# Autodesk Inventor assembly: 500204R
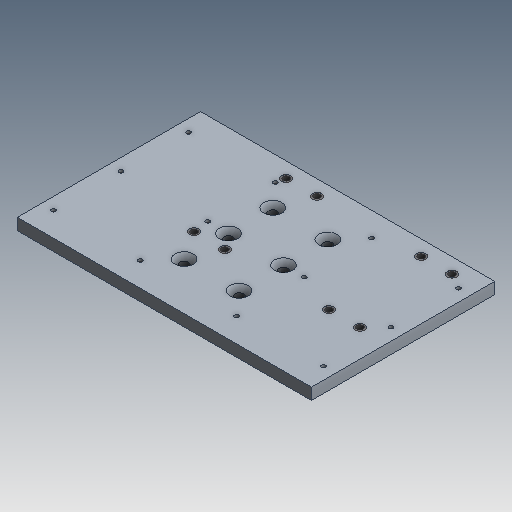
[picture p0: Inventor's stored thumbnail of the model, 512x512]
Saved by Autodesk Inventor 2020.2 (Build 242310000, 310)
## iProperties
Created: 1999-12
Part Number: 500204R
Description: PLT-CP,FA,XX,05,120,075,PLATE,MNT
Document SubType Name: Assembly
Designer: tgregory
Mass: 1875.54 g
Surface Area: 1401.55 cm^2
Volume: 683.002 cm^3
Density: 2.74602 g/cm^3
Control State: 0
Checked Out: False
Master: False
Shininess: 0.0
Length Units: 11272
Angle Units: 11279
Time Units: 11290
Mass Units: 11286
Length Display Precision: 3
Angle Display Precision: 2
Compacted: True
Dimensions: 7,5x0,5x12 in
Mass: 4,135 lb
DocNumber: 500204R.iam
Folder: 01 - Themengebiete\Simplification\01 - Packaging machine\
VDS_Category: 3D Komponenten
Density: 0.0
Volumn: 0.0
Area: 0.0
PropertySet Name: Model Information
Author: tgregory
Revision Number: -
Title: PLT-CP,FA,XX,05,120,075,PLATE,MNT
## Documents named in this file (4)
- D:\07 - DEMODATEN\OTX 2019 - Dataset - UPDATE - Dez2019\Designs\07-Packing machine\500204R.iam
- D:\07 - DEMODATEN\OTX 2019 - Dataset - UPDATE - Dez2019\Designs\07-Packing machine\Parts\ADSK-011301.ipt
- D:\07 - DEMODATEN\OTX 2019 - Dataset - UPDATE - Dez2019\Designs\07-Packing machine\Parts\ADSK-011735.ipt
- D:\07 - DEMODATEN\OTX 2019 - Dataset - UPDATE - Dez2019\Designs\07-Packing machine\Parts\ADSK-011736.ipt
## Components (21 placed, 3 different names)
1. ADSK-011301:1 — Insert:1, Insert:2, Insert:3, Insert:4, Insert:5, Insert:6, Insert:7, Insert:8, Insert:9, Insert:10, Insert:11, Insert:12, Einfügen:13, Einfügen:14, Einfügen:15, Einfügen:16, Einfügen:17, Einfügen:18, Einfügen:19, Einfügen:20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
2. ADSK-011735:1 — Einfügen:19
3. ADSK-011735:2 — Einfügen:22
4. ADSK-011735:3 — Einfügen:20
5. ADSK-011735:4 — Einfügen:23
6. ADSK-011735:5 — Einfügen:24
7. ADSK-011735:6 — Einfügen:21
8. ADSK-011735:7 — Einfügen:18
9. ADSK-011735:8 — Einfügen:15
10. ADSK-011735:9 — Einfügen:17
11. ADSK-011735:10 — Einfügen:14
12. ADSK-011735:11 — Einfügen:16
13. ADSK-011735:12 — Einfügen:13
14. ADSK-011736:1 — Insert:3
15. ADSK-011736:2 — Insert:2
16. ADSK-011736:3 — Insert:4
17. ADSK-011736:4 — Insert:1
18. ADSK-011736:5 — Insert:7, Insert:11
19. ADSK-011736:6 — Insert:6, Insert:10
20. ADSK-011736:7 — Insert:5, Insert:9
21. ADSK-011736:8 — Insert:8, Insert:12
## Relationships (24: Insert 24)
- Insert:1: ADSK-011301:1 ↔ ADSK-011736:4
- Insert:2: ADSK-011301:1 ↔ ADSK-011736:2
- Insert:3: ADSK-011301:1 ↔ ADSK-011736:1
- Insert:4: ADSK-011301:1 ↔ ADSK-011736:3
- Insert:5: ADSK-011301:1 ↔ ADSK-011736:7
- Insert:6: ADSK-011301:1 ↔ ADSK-011736:6
- Insert:7: ADSK-011301:1 ↔ ADSK-011736:5
- Insert:8: ADSK-011301:1 ↔ ADSK-011736:8
- Insert:9: ADSK-011301:1 ↔ ADSK-011736:7
- Insert:10: ADSK-011301:1 ↔ ADSK-011736:6
- Insert:11: ADSK-011301:1 ↔ ADSK-011736:5
- Insert:12: ADSK-011301:1 ↔ ADSK-011736:8
- Einfügen:13 [Insert]: ADSK-011301:1 ↔ ADSK-011735:12
- Einfügen:14 [Insert]: ADSK-011301:1 ↔ ADSK-011735:10
- Einfügen:15 [Insert]: ADSK-011301:1 ↔ ADSK-011735:8
- Einfügen:16 [Insert]: ADSK-011301:1 ↔ ADSK-011735:11
- Einfügen:17 [Insert]: ADSK-011301:1 ↔ ADSK-011735:9
- Einfügen:18 [Insert]: ADSK-011301:1 ↔ ADSK-011735:7
- Einfügen:19 [Insert]: ADSK-011301:1 ↔ ADSK-011735:1
- Einfügen:20 [Insert]: ADSK-011301:1 ↔ ADSK-011735:3
- Einfügen:21 [Insert]: ADSK-011301:1 ↔ ADSK-011735:6
- Einfügen:22 [Insert]: ADSK-011301:1 ↔ ADSK-011735:2
- Einfügen:23 [Insert]: ADSK-011301:1 ↔ ADSK-011735:4
- Einfügen:24 [Insert]: ADSK-011301:1 ↔ ADSK-011735:5
